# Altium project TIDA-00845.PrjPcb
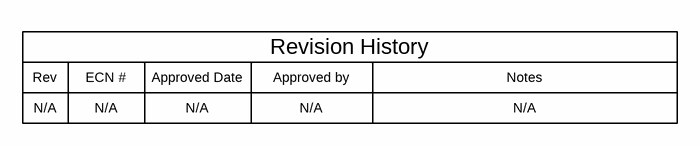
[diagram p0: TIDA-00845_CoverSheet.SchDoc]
TID: 00845; TechSupport: http://www.ti.com/support; SCH_Rev: A; PRJ_Title: USB2.0 Hub with STB Protection; PRJ_Number: TIDA-00845; PRJ_Engineer: Guy Yater; PRJ_Customer: Public Release; PCB_Rev: A; PCB_Layout: Guy Yater; EVM_Orderable: N/A; CopyrightYear: 2016
5 sheets, 144 parts. Net scope: flat (ports and power ports of the same name join across sheets).
Board file: TIDA-00845_TID.PcbDoc
Sheets:
  TIDA-00845_CoverSheet.SchDoc
  TIDA-00845_SCH.SchDoc
  TIDA-00845_TID_Hardware.SchDoc
  TIDA-00845_Enclosure_Machining.SchDoc
  TIDA-00845_Enclosure.SchDoc

## Sheet TIDA-00845_CoverSheet.SchDoc
size 431 x 279 mm; Date: Not shown in title block; ApprovedBy: Not shown in title block; CheckedBy: Not shown in title block; Author: Not shown in title block; CompanyName: Not shown in title block; Engineer: Not shown in title block; Organization: Not shown in title block; Address1: Not shown in title block; Address2: Not shown in title block; Address3: Not shown in title block; Address4: Not shown in title block; DocumentNumber: 1; Revision: Use project parameter SCH_Rev; SheetNumber: 1; SheetTotal: 3; PageSetup: Record=PageOptions¦CenterHorizontal=True¦CenterVertical=True¦PrintScale=1.00¦XCorrection=1.00¦YCorrection=1.00¦PrintKind=0¦BorderSize=5000000¦LeftOffset=0¦BottomOffset=0¦Orientation=2¦PaperLength=1000¦PaperWidth=1000¦Scale=100¦PaperSource=15¦PrintQuality=600¦MediaType=1¦DitherType=10¦PaperKind=Letter¦PrintScaleMode=1

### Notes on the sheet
- Rev
- N/A
- ECN #
- Approved Date
- Approved by
- Revision History
- Notes

## Sheet TIDA-00845_SCH.SchDoc
size 431 x 279 mm; Date: Not shown in title block; ApprovedBy: Not shown in title block; CheckedBy: Not shown in title block; Author: Not shown in title block; CompanyName: Not shown in title block; Engineer: Not shown in title block; Organization: Not shown in title block; Address1: Not shown in title block; Address2: Not shown in title block; Address3: Not shown in title block; Address4: Not shown in title block; DocumentNumber: 1; Revision: Use project parameter SCH_Rev; SheetNumber: 2; SheetTotal: 3; PageSetup: Record=PageOptions¦CenterHorizontal=True¦CenterVertical=True¦PrintScale=1.00¦XCorrection=1.00¦YCorrection=1.00¦PrintKind=0¦BorderSize=5000000¦LeftOffset=0¦BottomOffset=0¦Orientation=2¦PaperLength=1000¦PaperWidth=1000¦Scale=100¦PaperSource=15¦PrintQuality=600¦MediaType=1¦DitherType=10¦PaperKind=Letter¦PrintScaleMode=1
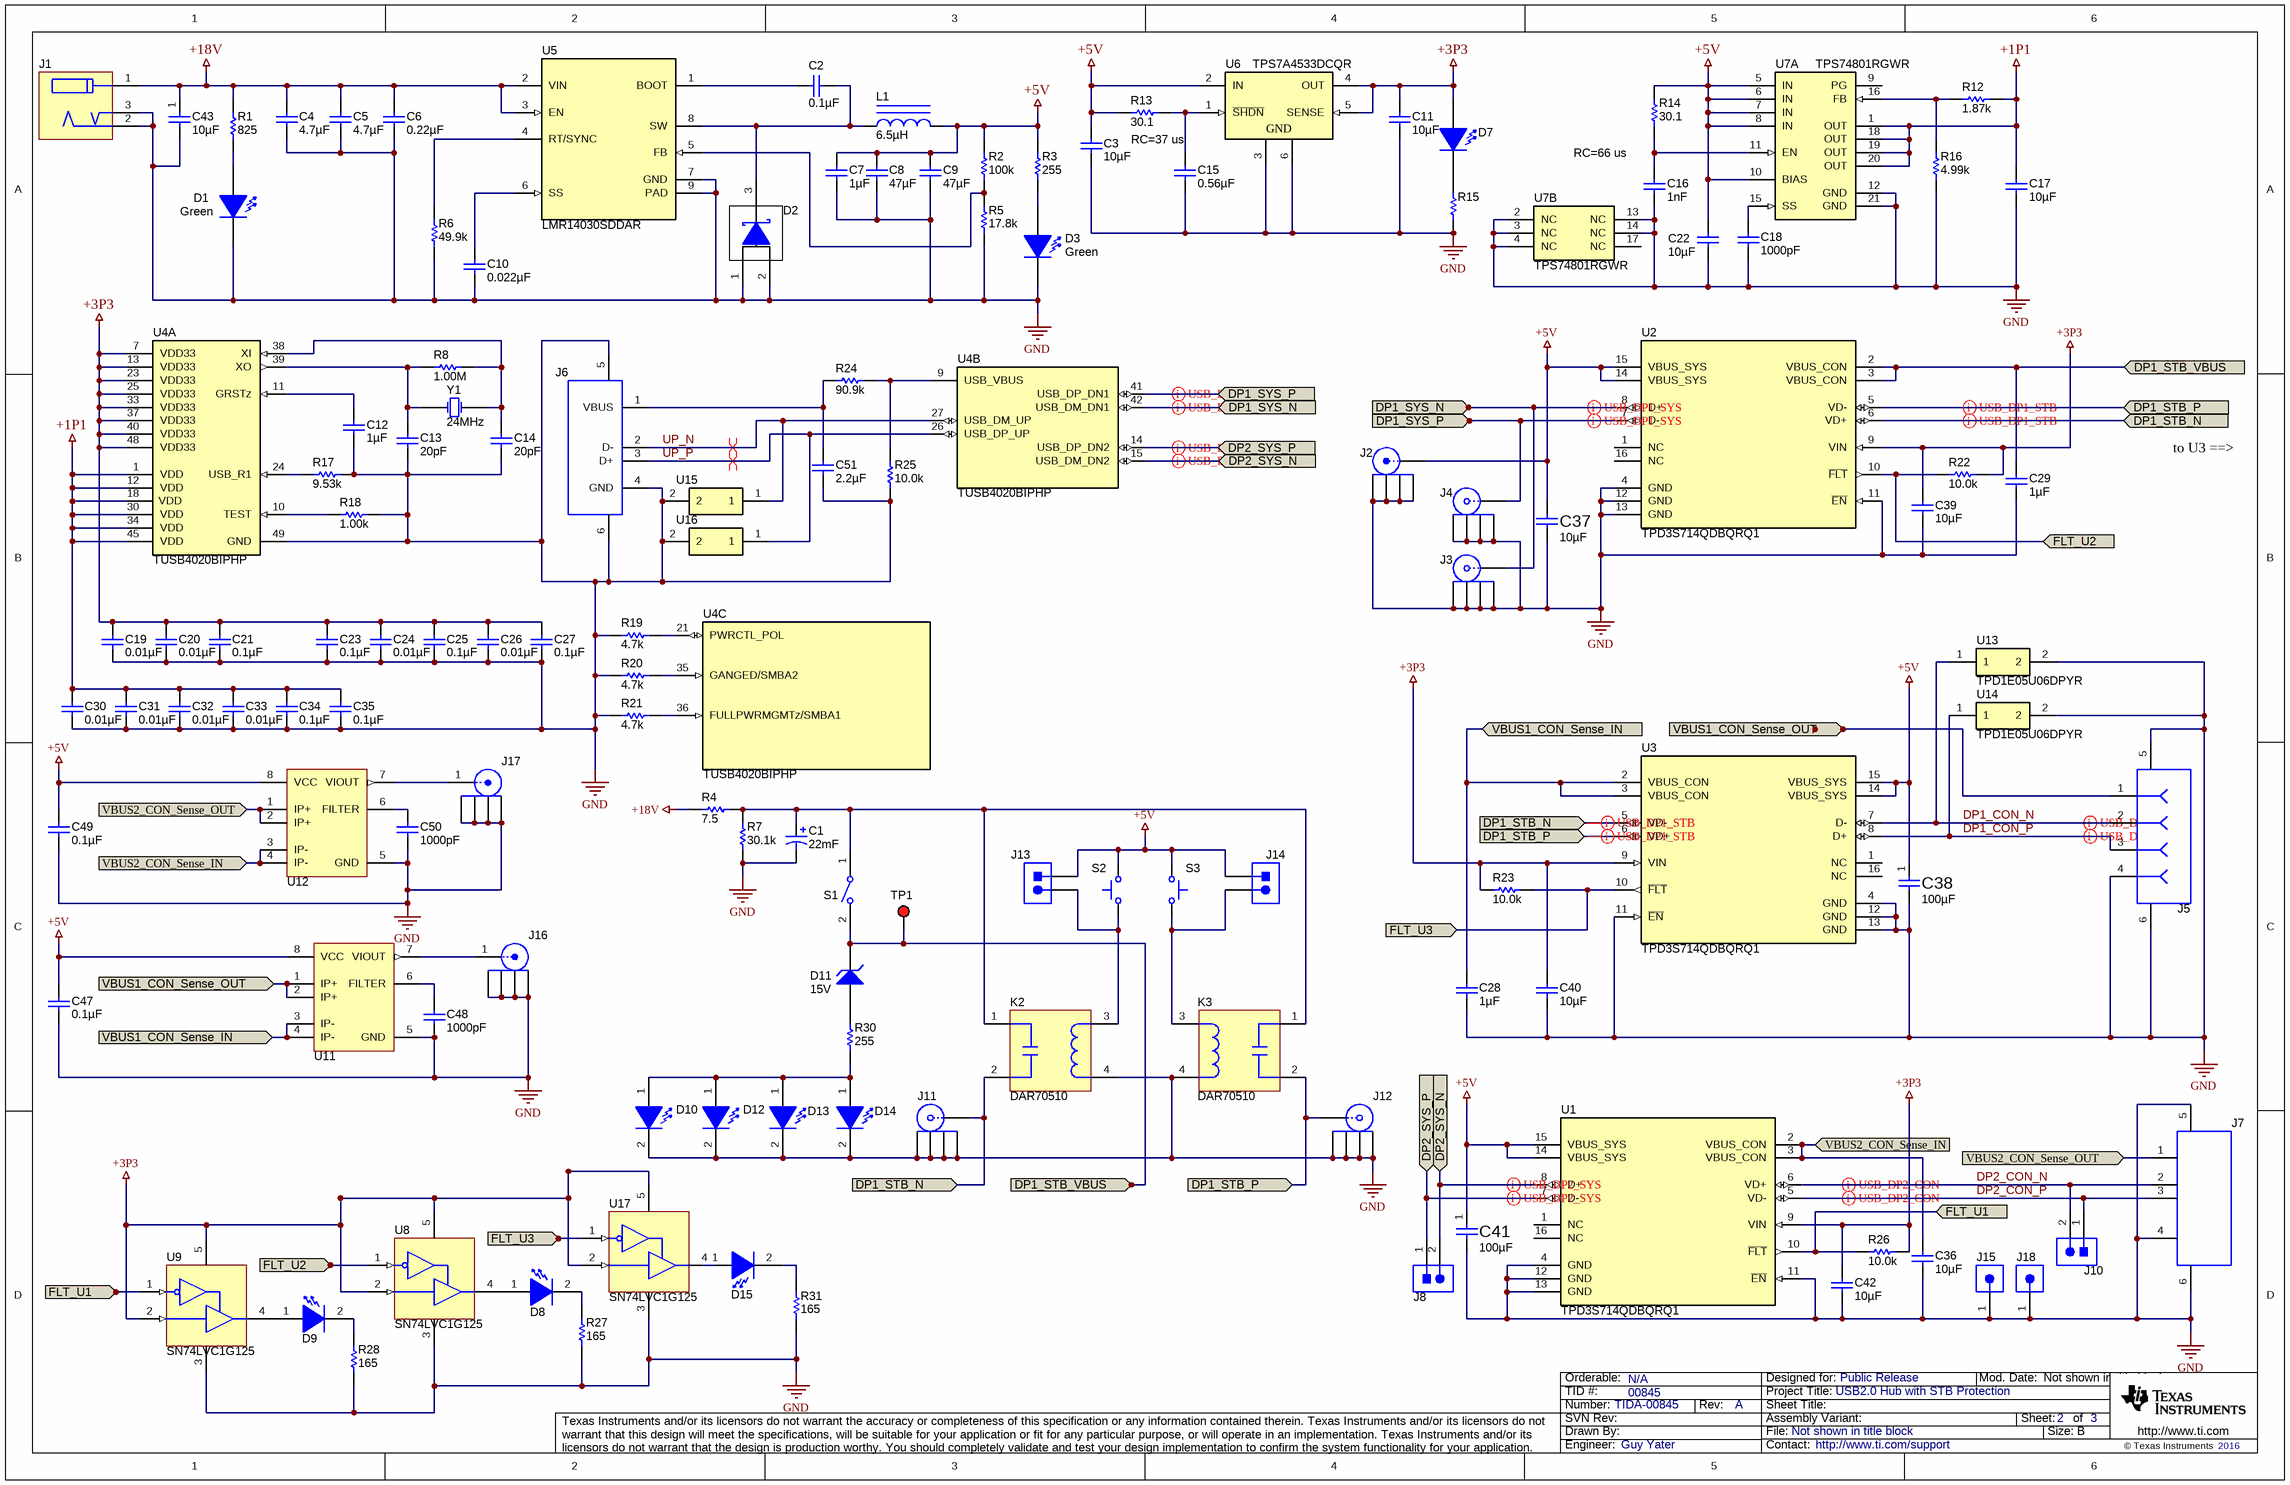
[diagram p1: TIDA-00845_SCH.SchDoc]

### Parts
C1  ValueDisplayed: 22mF  [EKMH350VSN223MA50T]  (hidden comment: B41231B5229M)
C2  ValueDisplayed: 0.1µF  [0603]  (hidden comment: GRM188R71C104KA01D)
C3  ValueDisplayed: 10µF  [0805_HV]  (hidden comment: 0805YD106MAT2A)
C4  ValueDisplayed: 4.7µF  [1210]  (hidden comment: GRM32ER71H475KA88L)
C5  ValueDisplayed: 4.7µF  [1210]  (hidden comment: GRM32ER71H475KA88L)
C6  ValueDisplayed: 0.22µF  [0805_HV]  (hidden comment: GRM21BR71H224KA01L)
C7  ValueDisplayed: 1µF  [0805_HV]  (hidden comment: GRM21BR71E105KA99L)
C8  ValueDisplayed: 47µF  [1210]  (hidden comment: GRM32ER61C476ME15L)
C9  ValueDisplayed: 47µF  [1210]  (hidden comment: GRM32ER61C476ME15L)
C10  ValueDisplayed: 0.022µF  [0402]  (hidden comment: GRM155R71C223KA01D)
C11  ValueDisplayed: 10µF  [0805_HV]  (hidden comment: 0805YD106MAT2A)
C12  ValueDisplayed: 1µF  [0402]  (hidden comment: GRM155R70J105MA12D)
C13  ValueDisplayed: 20pF  [0402]  (hidden comment: GRM1555C1H200JA01D)
C14  ValueDisplayed: 20pF  [0402]  (hidden comment: GRM1555C1H200JA01D)
C15  ValueDisplayed: 0.56µF  [1206]  (hidden comment: C1206C564K5RACTU)
C16  ValueDisplayed: 1nF  [1206_190]  (hidden comment: 202R18W102KV4E)
C17  ValueDisplayed: 10µF  [0805_HV]  (hidden comment: 0805YD106MAT2A)
C18  ValueDisplayed: 1000pF  [1206_190]  (hidden comment: 202R18W102KV4E)
C19  ValueDisplayed: 0.01µF  [0402]  (hidden comment: GRM155R71H103KA88D)
C20  ValueDisplayed: 0.01µF  [0402]  (hidden comment: GRM155R71H103KA88D)
C21  ValueDisplayed: 0.1µF  [0402]  (hidden comment: TMK105B7104MV-FR)
C22  ValueDisplayed: 10µF  [0805_HV]  (hidden comment: 0805YD106MAT2A)
C23  ValueDisplayed: 0.1µF  [0402]  (hidden comment: TMK105B7104MV-FR)
C24  ValueDisplayed: 0.01µF  [0402]  (hidden comment: GRM155R71H103KA88D)
C25  ValueDisplayed: 0.1µF  [0402]  (hidden comment: TMK105B7104MV-FR)
C26  ValueDisplayed: 0.01µF  [0402]  (hidden comment: GRM155R71H103KA88D)
C27  ValueDisplayed: 0.1µF  [0402]  (hidden comment: TMK105B7104MV-FR)
C28  ValueDisplayed: 1µF  [0603]  (hidden comment: UMK107AB7105KA-T)
C29  ValueDisplayed: 1µF  [0603]  (hidden comment: UMK107AB7105KA-T)
C30  ValueDisplayed: 0.01µF  [0402]  (hidden comment: GRM155R71H103KA88D)
C31  ValueDisplayed: 0.01µF  [0402]  (hidden comment: GRM155R71H103KA88D)
C32  ValueDisplayed: 0.01µF  [0402]  (hidden comment: GRM155R71H103KA88D)
C33  ValueDisplayed: 0.01µF  [0402]  (hidden comment: GRM155R71H103KA88D)
C34  ValueDisplayed: 0.1µF  [0402]  (hidden comment: TMK105B7104MV-FR)
C35  ValueDisplayed: 0.1µF  [0402]  (hidden comment: TMK105B7104MV-FR)
C36  ValueDisplayed: 10µF  [CKG57N]  (hidden comment: CKG57NX7R2A106M500JH)
C37  ValueDisplayed: 10µF  [1210_280]  (hidden comment: C1210C107M8PACTU)
C38  ValueDisplayed: 100µF  [1210_280]  (hidden comment: C1210C107M8PACTU)
C39  ValueDisplayed: 10µF  [0805L]  (hidden comment: C2012X7R0J106M125AB)
C40  ValueDisplayed: 10µF  [0805L]  (hidden comment: C2012X7R0J106M125AB)
C41  ValueDisplayed: 100µF  [1210_280]  (hidden comment: C1210C107M8PACTU)
C42  ValueDisplayed: 10µF  [0805L]  (hidden comment: C2012X7R0J106M125AB)
C43  ValueDisplayed: 10µF  [CKG57N]  (hidden comment: CKG57NX7R2A106M500JH)
C47  ValueDisplayed: 0.1µF  [0603]  (hidden comment: 06033C104JAT2A)
C48  ValueDisplayed: 1000pF  [0402]  (hidden comment: 885012205044)
C49  ValueDisplayed: 0.1µF  [0603]  (hidden comment: 06033C104JAT2A)
C50  ValueDisplayed: 1000pF  [0402]  (hidden comment: 885012205044)
C51  ValueDisplayed: 2.2µF  [0402]  (hidden comment: JMK105BJ225MV-F)
D1  value Green  [LED_LTST-C171]  (hidden comment: LTST-C171GKT)
D2  PDS560-13  [PowerDI5]  (value not drawn)
D3  value Green  [LED_LTST-C171]  (hidden comment: LTST-C171GKT)
D7  LTST-C171GKT  [LED_LTST-C171]  (value not drawn)
D8  VLMS1500-GS08  [VLMx1500_Red]  (value not drawn)
D9  VLMS1500-GS08  [VLMx1500_Red]  (value not drawn)
D10  VLMS1500-GS08  [VLMx1500_Red]  (value not drawn)
D11  value 15V  [SMA]  (hidden comment: 1SMA5929BT3G)
D12  VLMS1500-GS08  [VLMx1500_Red]  (value not drawn)
D13  VLMS1500-GS08  [VLMx1500_Red]  (value not drawn)
D14  VLMS1500-GS08  [VLMx1500_Red]  (value not drawn)
D15  VLMS1500-GS08  [VLMx1500_Red]  (value not drawn)
J1  PJ-202AH  [CONN_CUI-PJ-202AH]  (value not drawn)
J2  131-3701-261  [CONN_131-3701-261]  (value not drawn)
J3  131-5031-00  [Tek_131-5031-00]  (value not drawn)
J4  131-5031-00  [Tek_131-5031-00]  (value not drawn)
J5  292303-4  [CONN_TE_292303-4]  (value not drawn)
J6  67068-8000  [MOLEX_67068-8000]  (value not drawn)
J7  896-43-004-00-000000  [CONN_USB_896-43-004-00-000000]  (value not drawn)
J8  800-10-002-10-001000  [Mill-Max_800-10-002-10-001000]  (value not drawn)
J10  800-10-002-10-001000  [Mill-Max_800-10-002-10-001000]  (value not drawn)
J11  131-5031-00  [Tek_131-5031-00]  (value not drawn)
J12  131-5031-00  [Tek_131-5031-00]  (value not drawn)
J13  22-23-2021  [Molex_22-23-2021]  (value not drawn)
J14  22-23-2021  [Molex_22-23-2021]  (value not drawn)
J15  61300111121  [WURTH_61300111121]  (value not drawn)
J16  131-3701-261  [CONN_131-3701-261]  (value not drawn)
J17  131-3701-261  [CONN_131-3701-261]  (value not drawn)
J18  61300111121  [WURTH_61300111121]  (value not drawn)
K2  DAR70510  [DAR70510]
K3  DAR70510  [DAR70510]
L1  ValueDisplayed: 6.5µH  [WE-HCI_7050]  (hidden comment: 744314650)
R1  ValueDisplayed: 825  [0402]  (hidden comment: CRCW0402825RFKED)
R2  ValueDisplayed: 100k  [0402]  (hidden comment: CRCW0402100KDHEDP)
R3  ValueDisplayed: 255  [0402]  (hidden comment: CRCW0402255RFKED)
R4  ValueDisplayed: 7.5  [TEH100M7R50FE]  (hidden comment: TEH100M7R50FE)
R5  ValueDisplayed: 17.8k  [0402]  (hidden comment: CRCW040217K8FKED)
R6  ValueDisplayed: 49.9k  [0402]  (hidden comment: CRCW040249K9FKED)
R7  ValueDisplayed: 30.1k  [0402]  (hidden comment: CRCW040230K1FKED)
R8  ValueDisplayed: 1.00M  [0402]  (hidden comment: CRCW04021M00FKED)
R12  ValueDisplayed: 1.87k  [0402]  (hidden comment: CRCW04021K87FKED)
R13  ValueDisplayed: 30.1  [0402]  (hidden comment: CRCW040230R1FKED)
R14  ValueDisplayed: 30.1  [0402]  (hidden comment: CRCW040230R1FKED)
R15  CRCW0402330RJNED  [0402]  (value not drawn)
R16  ValueDisplayed: 4.99k  [0402]  (hidden comment: CRCW04024K99FKED)
R17  ValueDisplayed: 9.53k  [0402]  (hidden comment: CRCW04029K53FKED)
R18  ValueDisplayed: 1.00k  [0402]  (hidden comment: CRCW04021K00FKED)
R19  ValueDisplayed: 4.7k  [0402]  (hidden comment: CRCW04024K70JNED)
R20  ValueDisplayed: 4.7k  [0402]  (hidden comment: CRCW04024K70JNED)
R21  ValueDisplayed: 4.7k  [0402]  (hidden comment: CRCW04024K70JNED)
R22  value 10.0k  [0603]  (hidden comment: CRCW060310K0FKEA)
R23  value 10.0k  [0603]  (hidden comment: CRCW060310K0FKEA)
R24  ValueDisplayed: 90.9k  [0402]  (hidden comment: CRCW040290K9FKED)
R25  ValueDisplayed: 10.0k  [0402]  (hidden comment: CRCW040210K0DHEDP)
R26  value 10.0k  [0603]  (hidden comment: CRCW060310K0FKEA)
R27  ValueDisplayed: 165  [0402]  (hidden comment: CRCW0402165RFKED)
R28  ValueDisplayed: 165  [0402]  (hidden comment: CRCW0402165RFKED)
R30  ValueDisplayed: 255  [0402]  (hidden comment: CRCW0402255RFKED)
R31  ValueDisplayed: 165  [0402]  (hidden comment: CRCW0402165RFKED)
S1  GPB527C202BR  [GPB527C202BR]  (value not drawn)
S2  KSR221GLFS  [KSR]  (value not drawn)
S3  KSR221GLFS  [KSR]  (value not drawn)
TP1  5000  [Keystone5000]  (value not drawn)
U1  TPD3S714QDBQRQ1  [DBQ0016A_N]
U2  TPD3S714QDBQRQ1  [DBQ0016A_N]
U3  TPD3S714QDBQRQ1  [DBQ0016A_N]
U4  TUSB4020BIPHP  [PHP0048C_N]  (parts A,B,C of 4)
U5  LMR14030SDDAR  [DDA0008E_N]
U6  TPS7A4533DCQR  [DCQ0006A_N]
U7  TPS74801RGWR  [RGW0020A]  (parts A,B of 2)
U8  SN74LVC1G125  [DCK0005A_N]
U9  SN74LVC1G125  [DCK0005A_N]
U11  ACS712ELCTR-05B-T  [SOIC-8]  (value not drawn)
U12  ACS712ELCTR-05B-T  [SOIC-8]  (value not drawn)
U13  TPD1E05U06DPYR  [DPY0002A]
U14  TPD1E05U06DPYR  [DPY0002A]
U15  TPD1E05U06DPYR  [DPY0002A]  (value not drawn)
U16  TPD1E05U06DPYR  [DPY0002A]  (value not drawn)
U17  SN74LVC1G125  [DCK0005A_N]
Y1  Frequency: 24MHz  [445C25D24M00000]  (hidden comment: 445C25D24M00000)

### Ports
DP1_STB_N, DP1_STB_P, DP1_STB_VBUS, DP1_SYS_N, DP1_SYS_P, DP2_SYS_N, DP2_SYS_P, FLT_U1, FLT_U2, FLT_U3, VBUS1_CON_Sense_IN, VBUS1_CON_Sense_OUT, VBUS2_CON_Sense_IN, VBUS2_CON_Sense_OUT

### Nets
+1P1: C17.1 C30.2 C31.2 C32.2 C33.2 C34.2 C35.2 R12.2 U4.1(VDD) U4.12(VDD) U4.18(VDD) U4.30(VDD) U4.34(VDD) U4.45(VDD) U7.1(OUT) U7.18(OUT) U7.19(OUT) U7.20(OUT)
+3P3: C11.1 C19.2 C20.2 C21.2 C23.2 C24.2 C25.2 C26.2 C27.2 C39.1 C40.1 C42.1 D7.1(A) R22.2 R23.1 R26.2 U1.9(VIN) U2.9(VIN) U3.9(VIN) U4.7(VDD33) U4.13(VDD33) U4.23(VDD33) U4.25(VDD33) U4.33(VDD33) U4.37(VDD33) U4.40(VDD33) U4.48(VDD33) U6.4(OUT) U6.5(SENSE) U8.2(A) U8.5(VCC) U9.2(A) U9.5(VCC) U17.2(A) U17.5(VCC)
+5V: C3.1 C7.1 C8.1 C9.1 C22.1 C37.1 C38.1 C41.1 C47.1 C49.1 J2.1 J13.1 J14.1 L1.2 R2.1 R3.1 R13.2 R14.2 S2.2 S3.2 U1.14(VBUS_SYS) U1.15(VBUS_SYS) U2.14(VBUS_SYS) U2.15(VBUS_SYS) U3.14(VBUS_SYS) U3.15(VBUS_SYS) U6.2(IN) U7.5(IN) U7.6(IN) U7.7(IN) U7.8(IN) U7.10(BIAS) U11.8(VCC) U12.8(VCC)
+18V: C4.2 C5.2 C6.2 C43.1 J1.1 R1.2 R4.1 U5.2(VIN) U5.3(EN)
GND: C1.2(-) C3.2 C4.1 C5.1 C6.1 C7.2 C8.2 C9.2 C10.1 C11.2 C12.1 C13.2 C14.2 C15.1 C16.1 C17.2 C18.1 C19.1 C20.1 C21.1 C22.2 C23.1 C24.1 C25.1 C26.1 C27.1 C28.2 C29.2 C30.1 C31.1 C32.1 C33.1 C34.1 C35.1 C36.2 C37.2 C38.2 C39.2 C40.2 C41.2 C42.2 C43.2 C47.2 C48.2 C49.2 C50.2 C51.2 D1.2(K) D2.1(A) D2.2(A) D3.2(K) D10.2(K) D12.2(K) D13.2(K) D14.2(K) J1.2 J1.3 J2.2 J2.3 J2.4 J2.5 J3.2 J3.3 J3.4 J3.5 J4.2 J4.3 J4.4 J4.5 J5.4 J5.5 J5.6 J6.4(GND) J6.5(Shield) J6.6(Shield) J7.4(ID) J7.5(Shield) J7.6(Shield) J11.2 J11.3 J11.4 J11.5 J12.2 J12.3 J12.4 J12.5 J15.1 J16.2 J16.3 J16.4 J16.5 J17.2 J17.3 J17.4 J17.5 J18.1 K2.4 K3.4 R5.2 R6.2 R7.1 R15.1 R16.1 R17.2 R18.2 R19.1 R20.1 R21.1 R25.1 R27.2 R28.2 R31.2 U1.4(GND) U1.11(~{EN}) U1.12(GND) U1.13(GND) U2.4(GND) U2.11(~{EN}) U2.12(GND) U2.13(GND) U3.4(GND) U3.11(~{EN}) U3.12(GND) U3.13(GND) U4.49(GND) U5.7(GND) U5.9(PAD) U6.3(GND) U6.6(GND) U7.2(NC) U7.3(NC) U7.4(NC) U7.12(GND) U7.13(NC) U7.14(NC) U7.21(GND) U8.3(GND) U9.3(GND) U11.5(GND) U12.5(GND) U13.2 U14.2 U15.2 U16.2 U17.3(GND)
DP1_CON_N: J5.2 U3.7(D-) U13.1
DP1_CON_P: J5.3 U3.8(D+) U14.1
DP1_STB_N: J11.1 K2.2 U2.6(VD+) U3.5(VD-) ; port DP1_STB_N
DP1_STB_P: J12.1 K3.2 U2.5(VD-) U3.6(VD+) ; port DP1_STB_P
DP1_STB_VBUS: C29.1 D11.1(K) S1.2 TP1.1 U2.2(VBUS_CON) U2.3(VBUS_CON) ; port DP1_STB_VBUS
DP1_SYS_N: J3.1 U2.8(D+) U4.42(USB_DM_DN1) ; port DP1_SYS_N
DP1_SYS_P: J4.1 U2.7(D-) U4.41(USB_DP_DN1) ; port DP1_SYS_P
DP2_CON_N: J7.2(D-) J10.2 U1.6(VD+)
DP2_CON_P: J7.3(D+) J10.1 U1.5(VD-)
DP2_SYS_N: J8.2 U1.8(D+) U4.15(USB_DM_DN2) ; port DP2_SYS_N
DP2_SYS_P: J8.1 U1.7(D-) U4.14(USB_DP_DN2) ; port DP2_SYS_P
FLT_U1: R26.1 U1.10(~{FLT}) U9.1(~{OE}) ; port FLT_U1
FLT_U2: R22.1 U2.10(~{FLT}) U8.1(~{OE}) ; port FLT_U2
FLT_U3: R23.2 U3.10(~{FLT}) U17.1(~{OE}) ; port FLT_U3
UP_N: J6.2(D-) U4.27(USB_DM_UP) U15.1
UP_P: J6.3(D+) U4.26(USB_DP_UP) U16.1
VBUS1_CON_Sense_IN: C28.1 U3.2(VBUS_CON) U3.3(VBUS_CON) U11.3(IP-) U11.4(IP-) ; port VBUS1_CON_Sense_IN
VBUS1_CON_Sense_OUT: J5.1 U11.1(IP+) U11.2(IP+) ; port VBUS1_CON_Sense_OUT
VBUS2_CON_Sense_IN: C36.1 U1.2(VBUS_CON) U1.3(VBUS_CON) U12.3(IP-) U12.4(IP-) ; port VBUS2_CON_Sense_IN
VBUS2_CON_Sense_OUT: J7.1(VBUS) U12.1(IP+) U12.2(IP+) ; port VBUS2_CON_Sense_OUT
NetC1_1: C1.1(+) K2.1 K3.1 R4.2 R7.2 S1.1
NetC2_1: C2.1 D2.3(K) L1.1 U5.8(SW)
NetC2_2: C2.2 U5.1(BOOT)
NetC10_2: C10.2 U5.6(SS)
NetC12_2: C12.2 U4.11(GRSTz)
NetC13_1: C13.1 R8.1 U4.39(XO) Y1.1(OSC1)
NetC14_1: C14.1 R8.2 U4.38(XI) Y1.2(OSC2)
NetC15_2: C15.2 R13.1 U6.1(~{SHDN})
NetC16_2: C16.2 R14.1 U7.11(EN)
NetC18_2: C18.2 U7.15(SS)
NetC48_1: C48.1 U11.6(FILTER)
NetC50_1: C50.1 U12.6(FILTER)
NetC51_1: C51.1 J6.1(VBUS) R24.1
NetD1_1: D1.1(A) R1.1
NetD3_1: D3.1(A) R3.2
NetD7_2: D7.2(K) R15.2
NetD8_1: D8.1(A) U8.4(Y)
NetD8_2: D8.2(K) R27.1
NetD9_1: D9.1(A) U9.4(Y)
NetD9_2: D9.2(K) R28.1
NetD10_1: D10.1(A) D12.1(A) D13.1(A) D14.1(A) R30.2
NetD11_2: D11.2(A) R30.1
NetD15_1: D15.1(A) U17.4(Y)
NetD15_2: D15.2(K) R31.1
NetJ13_2: J13.2 K2.3 S2.1
NetJ14_2: J14.2 K3.3 S3.1
NetJ16_1: J16.1 U11.7(VIOUT)
NetJ17_1: J17.1 U12.7(VIOUT)
NetR2_2: R2.2 R5.1 U5.5(FB)
NetR6_1: R6.1 U5.4(RT/SYNC)
NetR12_1: R12.1 R16.2 U7.16(FB)
NetR17_1: R17.1 U4.24(USB_R1)
NetR18_1: R18.1 U4.10(TEST)
NetR19_2: R19.2 U4.21(PWRCTL_POL)
NetR20_2: R20.2 U4.35(GANGED/SMBA2)
NetR21_2: R21.2 U4.36(FULLPWRMGMTz/SMBA1)
NetR24_2: R24.2 R25.2 U4.9(USB_VBUS)

Not connected (* = marked no-connect by the designer): U1 1(NC) 16(NC); U2 1(NC) 16(NC); U3 1(NC) 16(NC); U7 9(PG) 17(NC)

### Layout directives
differential pair: DP1_CON_N, DP1_CON_P, DP1_STB_N, DP1_STB_P, DP1_SYS_N, DP1_SYS_P, DP2_CON_N, DP2_CON_P, DP2_SYS_N, DP2_SYS_P, UP_N, UP_P

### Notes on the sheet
- RC=37 us
- RC=66 us
- to U3 ==>

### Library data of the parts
C1 = EMVA6R3GTR103MMN0S: CAP, AL, 10000 µF, 6.3 V, +/- 20%, SMD; Manufacturer: EPCOS (TDK); Polarized: Y; CompType: Capacitor; Value: 22000uF; U/M: EA; Cap_F: .022; Tolerance_%: 20; Value1: Unknown; VDC_V: 25V; IRMS_A: 2; TaMin_C: -40; TaMax_C: 85; Cap_Case: MN0; AEC Category: Q200
C2 = GRM188R71C104KA01D: CAP, CERM, 0.1 µF, 16 V, +/- 10%, X7R, 0603; Manufacturer: MuRata; Polarized: N; CompType: Capacitor; Value: 0.1uF; U/M: EA; Cap_F: 0.0000001; Tolerance_%: 10; Value1: Unknown; VDC_V: 16; Value2: 16V; TaMin_C: -55; TaMax_C: 125; AEC Category: Q200
C3 C11 C17 C22 = 0805YD106MAT2A: CAP, CERM, 10 µF, 16 V, +/- 20%, X5R, 0805; Manufacturer: AVX; Polarized: N; CompType: Capacitor; Value: 10uF; U/M: EA; Cap_F: 0.00001; Tolerance_%: 20; Value1: Unknown; VDC_V: 16; Value2: 16V; TaMin_C: -55; TaMax_C: 85; Cap_Case: 0805; AEC Category: Q200
C4 C5 = GRM32ER71H475KA88L: CAP, CERM, 4.7 µF, 50 V, +/- 10%, X7R, 1210; Manufacturer: MuRata; Polarized: N; CompType: Capacitor; Value: 4.7uF; U/M: EA; Cap_F: 0.0000047; Tolerance_%: 10; ESR_ohm: 0.002; Value1: 0.002 ohm; VDC_V: 50; Value2: 50V; TaMin_C: -55; TaMax_C: 125; AEC Category: Q200
C6 = GRM21BR71H224KA01L: CAP, CERM, 0.22 µF, 50 V, +/- 10%, X7R, 0805; Manufacturer: MuRata; Polarized: N; CompType: Capacitor; Value: 0.22uF; U/M: EA; Cap_F: 0.00000022; Tolerance_%: 10; Value1: Unknown; VDC_V: 50; Value2: 50V; TaMin_C: -55; TaMax_C: 125; Cap_Case: 0805; AEC Category: Q200
C7 = GRM21BR71E105KA99L: CAP, CERM, 1 µF, 25 V, +/- 10%, X7R, 0805; Manufacturer: MuRata; Polarized: N; CompType: Capacitor; Value: 1uF; U/M: EA; Cap_F: 0.000001; Tolerance_%: 10; Value1: Unknown; VDC_V: 25; Value2: 25V; TaMin_C: -55; TaMax_C: 125; Cap_Case: 0805; AEC Category: Q200
C8 C9 = GRM32ER61C476ME15L: CAP, CERM, 47 µF, 16 V, +/- 20%, X5R, 1210; Manufacturer: MuRata; Polarized: N; CompType: Capacitor; Value: 47uF; U/M: EA; Cap_F: 0.000047; Tolerance_%: 20; ESR_ohm: 0.002; Value1: 0.002 ohm; VDC_V: 16; Value2: 16V; TaMin_C: -55; TaMax_C: 85; AEC Category: Q200
C10 = GRM155R71C223KA01D: CAP, CERM, 0.022 µF, 16 V, +/- 10%, X7R, 0402; Manufacturer: MuRata; Polarized: N; CompType: Capacitor; Value: 0.022uF; U/M: EA; Cap_F: 0.000000022; Tolerance_%: 10; Value1: Unknown; VDC_V: 16; Value2: 16V; TaMin_C: -55; TaMax_C: 125; AEC Category: Q200
C12 = GRM155R70J105MA12D: CAP, CERM, 1 µF, 6.3 V, +/- 20%, X7R, 0402; Manufacturer: MuRata; Polarized: N; CompType: Capacitor; Value: 1uF; U/M: EA; Cap_F: 0.000001; Tolerance_%: 20; Value1: Unknown; VDC_V: 6.3; Value2: 6.3V; TaMin_C: -55; TaMax_C: 125; AEC Category: Q200
C13 C14 = GRM1555C1H200JA01D: CAP, CERM, 20 pF, 50 V, +/- 5%, C0G/NP0, 0402; Manufacturer: MuRata; Polarized: N; CompType: Capacitor; Value: 20pF; U/M: EA; Cap_F: 0.00000000002; Tolerance_%: 5; Value1: Unknown; VDC_V: 50; Value2: 50V; TaMin_C: -55; TaMax_C: 125; AEC Category: Q200
C15 = 12063C564KAT2A: CAP, CERM, 0.56 µF, 25 V, +/- 10%, X7R, 1206; Manufacturer: AVX; Polarized: N; CompType: Capacitor; Value: 0.56uF; U/M: EA; Cap_F: 0.00000056; Tolerance_%: 10; ESR_ohm: 0.017; Value1: 0.017 ohm; VDC_V: 25; Value2: 25V; TaMin_C: -55; TaMax_C: 125; AEC Category: Q200
C16 C18 = 202R18W102KV4E: CAP, CERM, 1000 pF, 2000 V, +/- 10%, X7R, 1206_190; Manufacturer: Johanson Technology; Polarized: N; CompType: Capacitor; Value: 1000pF; U/M: EA; Cap_F: 0.000000001; Tolerance_%: 10; Value1: Unknown; VDC_V: 2000; Value2: 2000V; TaMin_C: -55; TaMax_C: 125; Cap_Case: 1206; AEC Category: Q200
C19 C20 C24 C26 C30-C33 = GRM155R71H103KA88D: CAP, CERM, 0.01 µF, 50 V, +/- 10%, X7R, 0402; Manufacturer: MuRata; Polarized: N; CompType: Capacitor; Value: 0.01uF; U/M: EA; Cap_F: 0.00000001; Tolerance_%: 10; Value1: Unknown; VDC_V: 50; Value2: 50V; TaMin_C: -55; TaMax_C: 125; AEC Category: Q200
C21 C23 C25 C27 C34 C35 = TMK105B7104MV-FR: CAP, CERM, 0.1 µF, 25 V, +/- 20%, X7R, 0402; Manufacturer: Taiyo Yuden; Polarized: N; CompType: Capacitor; Value: 0.1uF; U/M: EA; Cap_F: 0.0000001; Tolerance_%: 20; Value1: Unknown; VDC_V: 25; Value2: 25V; TaMin_C: -55; TaMax_C: 125; AEC Category: Q200
C28 C29 = UMK107AB7105KA-T: CAP, CERM, 1 µF, 50 V, +/- 10%, X7R, 0603; Manufacturer: Taiyo Yuden; Polarized: N; CompType: Capacitor; Value: 1uF; U/M: EA; Cap_F: 0.000001; Tolerance_%: 10; Value1: Unknown; VDC_V: 50; Value2: 50V; TaMin_C: -55; TaMax_C: 125; AEC Category: Q200
C36 C43 = CKG57NX7R2A106M500JH: CAP, CERM, 10 µF, 100 V, +/- 20%, X7R, 6x5x5mm; Manufacturer: TDK; Polarized: N; CompType: Capacitor; Value: 10uF; U/M: EA; Cap_F: 0.00001; Tolerance_%: 20; Value1: Unknown; VDC_V: 100; Value2: 100V; TaMin_C: -55; TaMax_C: 125; Cap_Case: 2220; AEC Category: Q200
C37 C38 C41 = C1210C107M8PACTU: CAP, CERM, 100 µF, 10 V, +/- 20%, X5R, 1210; Manufacturer: Wurth Elektronik; Polarized: N; CompType: Capacitor; Value: 100uF; U/M: EA; Cap_F: 0.0001; Tolerance_%: 20; Value1: Unknown; VDC_V: 10; Value2: 10V; TaMin_C: -55; TaMax_C: 85; Cap_Case: 1210
C39 C40 C42 = C2012X7R0J106M125AB: CAP, CERM, 10 µF, 6.3 V, +/- 20%, X7R, 0805; Manufacturer: TDK; Polarized: N; CompType: Capacitor; Value: 10uF; U/M: EA; Cap_F: 0.00001; Tolerance_%: 20; Value1: Unknown; VDC_V: 6.3; Value2: 6.3V; TaMin_C: -55; TaMax_C: 125; Cap_Case: 0805
C47 C49 = 06033C104JAT2A: CAP, CERM, 0.1 µF, 25 V, +/- 5%, X7R, 0603; Manufacturer: AVX; Polarized: N; CompType: Capacitor; Value: 0.1uF; U/M: EA; Cap_F: 0.0000001; Tolerance_%: 5; ESR_ohm: 0.05; Value1: 0.05 ohm; VDC_V: 25; Value2: 25V; TaMin_C: -55; TaMax_C: 125; AEC Category: Q200
C48 C50 = 885012205044: CAP, CERM, 1000 pF, 25 V, +/- 10%, X7R, 0402; Manufacturer: Wurth Elektronik; Polarized: N; CompType: Capacitor; Value: 1000pF; U/M: EA; Cap_F: 0.000000001; Tolerance_%: 10; Value1: Unknown; VDC_V: 25; Value2: 25V; TaMin_C: -55; TaMax_C: 125; AEC Category: Q200
C51 = JMK105BJ225MV-F: CAP, CERM, 2.2 µF, 6.3 V, +/- 20%, X5R, 0402; Manufacturer: Taiyo Yuden; Polarized: N; CompType: Capacitor; Value: 2.2uF; U/M: EA; Cap_F: 0.0000022; Tolerance_%: 20; ESR_ohm: 0.00152; Value1: 0.00152 ohm; VDC_V: 6.3; Value2: 6.3V; TaMin_C: -55; TaMax_C: 125; AEC Category: Q200
D1 D3 D7 = LTST-C171GKT: LED, Green, SMD; Manufacturer: Lite-On; Type: AlInGaP; Vf_V: 2.1; Value2: 2.1V; Io_A: 20; Value1: W; U/M: EA
D2 = PDS560-13: Diode, Schottky, 60 V, 5 A, PowerDI5; Manufacturer: Diodes Inc.; U/M: EA; Vf_V: 0.67; Value: 60V; Value1: 5A; Value2: 0.67V; Io_A: 5; Vr_V: 60; TJmax_C: 150; AEC Category: Q101
D8-D10 D12-D15 = VLMS1500-GS08: LED, Super Red, SMD; Manufacturer: Vishay-Semiconductor; Type: AlInGaP; Vf_V: 2; Value2: 2V; Io_A: 0.02; Value1: W; U/M: EA
D11 = 1SMA5929BT3G: Diode, Zener, 15 V, 500 mW, SMA; Manufacturer: ON Semiconductor; SymbolCreator: a0412235; U/M: EA; Power_W: 0.5; Vz_V: 15; Value1: 0.5W; AEC Category: Q101
J1 = PJ-202AH: Connector, DC Jack 2.1X5.5 mm, TH; Manufacturer: CUI Inc.; SymbolCreator: a0799628; CompType: Power Jack; U/M: EA
J2 J16 J17 = 131-3701-261: Connector, SMB,Vertical RCP 0-4GHz, 50 ohm, TH; Manufacturer: Emerson Network Power; U/M: EA
J3 J4 J11 J12 = 131-5031-00: Compact Probe Tip Circuit Board Test Points, TH, 25 per; Manufacturer: Tektronix; U/M: EA
J5 = 292303-4: Connector, Receptacle, USB Type A, R/A, Top Mount TH; Manufacturer: TE Connectivity; SymbolCreator: a0412235; U/M: EA
J6 = 67068-8000: Connector, Receptacle, USB TYPE B, R/A, Top Mount TH; Manufacturer: Molex; SymbolCreator: a0412235; U/M: EA
J7 = 896-43-004-00-000000: Connector, Receptacle, USB TYPE A, 4POS SMD; Manufacturer: Mill-Max; SymbolCreator: a0412235; U/M: EA
J8 J10 = 800-10-002-10-001000: Header, 100mil, 2x1, TH; Manufacturer: Mill-Max; SymbolCreator: a0412235; U/M: EA
J13 J14 = 22-23-2021: Header, 2.54mm, 2x1, Vertical, TH; Manufacturer: Molex; SymbolCreator: a0412235; U/M: EA
J15 J18 = 61300111121: Header, 2.54 mm, 1x1, Gold, TH; Manufacturer: Wurth Elektronik; SymbolCreator: a0412235; U/M: EA
K2 K3 = DAR70510: Manufacturer: Cynergy 3; SymbolCreator: a0273549; CompType: Used in some BOM reports.  Useful for finding later.; U/M: EA, IN, or GM
L1 = 744314650: Inductor, Shielded Drum Core, Superflux, 6.5 µH, 6 A, 0.0225 ohm, SMD; Manufacturer: Wurth Elektronik; Value: 6.5uH; Ind_H: 6.5E-6; Imax_A: 6; Irms: 6A @ 50C rise; Isat: 6A @ 30% inductance drop; DCR_ohm: 0.0225; Value2: 6A; AEC Category: Q200
R1 = CRCW0402825RFKED: RES, 825, 1%, 0.063 W, 0402; Manufacturer: Vishay-Dale; CompType: Resistor; Value: 825; Value_Code: 825R; Tolerance_%: 1; Power_W: 0.063; Value2: 0.063W; VDC_V: 50; TempCo: 100 ppm/C; EIA_Code: E96; U/M: EA; AEC Category: Q200
R2 = CRCW0402100KDHEDP: RES, 100 k, 0.5%, 0.063 W, 0402; Manufacturer: Vishay-Dale; CompType: Resistor; Value: 100k; Res_ohm: 100000; Tolerance_%: 0.5; Power_W: 0.063; Value2: 0.063W; VDC_V: 50; TempCo: 50 ppm/C; EIA_Code: E192; U/M: EA; AEC Category: Q200
R3 R30 = CRCW0402255RFKED: RES, 255, 1%, 0.063 W, 0402; Manufacturer: Vishay-Dale; CompType: Resistor; Value: 255; Value_Code: 255R; Tolerance_%: 1; Power_W: 0.063; Value2: 0.063W; VDC_V: 50; TempCo: 100 ppm/C; EIA_Code: E96; U/M: EA; AEC Category: Q200
R4 = SQP10AJB-7R5: RES, 7.5, 5%, 10 W, RES 48x9.5x9mm; Manufacturer: Ohmite; CompType: Resistor; Value: 7.5; Value_Code: 7R50; Tolerance_%: 5; Power_W: 100; Value2: 10W; VDC_V: 500; TempCo: 300 ppm/C; EIA_Code: E24; U/M: EA; AEC Category: Q200
R5 = CRCW040217K8FKED: RES, 17.8 k, 1%, 0.063 W, 0402; Manufacturer: Vishay-Dale; CompType: Resistor; Value: 17.8k; Res_ohm: 17800; Value_Code: 17k8; Tolerance_%: 1; Power_W: 0.063; Value2: 0.063W; VDC_V: 50; TempCo: 100 ppm/C; EIA_Code: E96; U/M: EA; AEC Category: Q200
R6 = CRCW040249K9FKED: RES, 49.9 k, 1%, 0.063 W, 0402; Manufacturer: Vishay-Dale; CompType: Resistor; Value: 49.9k; Res_ohm: 49900; Value_Code: 49k9; Tolerance_%: 1; Power_W: 0.063; Value2: 0.063W; VDC_V: 50; TempCo: 100 ppm/C; EIA_Code: E96; U/M: EA; AEC Category: Q200
R7 = CRCW040230K1FKED: RES, 30.1 k, 1%, 0.063 W, 0402; Manufacturer: Vishay-Dale; CompType: Resistor; Value: 30.1k; Res_ohm: 30100; Value_Code: 30k1; Tolerance_%: 1; Power_W: 0.063; Value2: 0.063W; VDC_V: 50; TempCo: 100 ppm/C; EIA_Code: E96; U/M: EA; AEC Category: Q200
R8 = CRCW04021M00FKED: RES, 1.00 M, 1%, 0.063 W, 0402; Manufacturer: Vishay-Dale; CompType: Resistor; Value: 1.00Meg; Res_ohm: 1000000; Value_Code: 1M00; Tolerance_%: 1; Power_W: 0.063; Value2: 0.063W; VDC_V: 50; TempCo: 100 ppm/C; EIA_Code: E96; U/M: EA; AEC Category: Q200
R12 = CRCW04021K87FKED: RES, 1.87 k, 1%, 0.063 W, 0402; Manufacturer: Vishay-Dale; CompType: Resistor; Value: 1.87k; Res_ohm: 1870; Value_Code: 1k87; Tolerance_%: 1; Power_W: 0.063; Value2: 0.063W; VDC_V: 50; TempCo: 100 ppm/C; EIA_Code: E96; U/M: EA; AEC Category: Q200
R13 R14 = CRCW040230R1FKED: RES, 30.1, 1%, 0.063 W, 0402; Manufacturer: Vishay-Dale; CompType: Resistor; Value: 30.1; Value_Code: 30R1; Tolerance_%: 1; Power_W: 0.063; Value2: 0.063W; VDC_V: 50; TempCo: 100 ppm/C; EIA_Code: E96; U/M: EA; AEC Category: Q200
R15 = CRCW0402330RJNED: RES, 330, 5%, 0.063 W, 0402; Manufacturer: Vishay-Dale; CompType: Resistor; Value: 330; Value_Code: 330R; Tolerance_%: 5; Power_W: 0.063; Value2: 0.063W; VDC_V: 50; TempCo: 200 ppm/C; EIA_Code: E24; U/M: EA; AEC Category: Q200
R16 = CRCW04024K99FKED: RES, 4.99 k, 1%, 0.063 W, 0402; Manufacturer: Vishay-Dale; CompType: Resistor; Value: 4.99k; Res_ohm: 4990; Value_Code: 4k99; Tolerance_%: 1; Power_W: 0.063; Value2: 0.063W; VDC_V: 50; TempCo: 100 ppm/C; EIA_Code: E96; U/M: EA; AEC Category: Q200
R17 = CRCW04029K53FKED: RES, 9.53 k, 1%, 0.063 W, 0402; Manufacturer: Vishay-Dale; CompType: Resistor; Value: 9.53k; Res_ohm: 9530; Value_Code: 9k53; Tolerance_%: 1; Power_W: 0.063; Value2: 0.063W; VDC_V: 50; TempCo: 100 ppm/C; EIA_Code: E96; U/M: EA; AEC Category: Q200
R18 = CRCW04021K00FKED: RES, 1.00 k, 1%, 0.063 W, 0402; Manufacturer: Vishay-Dale; CompType: Resistor; Value: 1.00k; Res_ohm: 1000; Value_Code: 1k00; Tolerance_%: 1; Power_W: 0.063; Value2: 0.063W; VDC_V: 50; TempCo: 100 ppm/C; EIA_Code: E96; U/M: EA; AEC Category: Q200
R19-R21 = CRCW04024K70JNED: RES, 4.7 k, 5%, 0.063 W, 0402; Manufacturer: Vishay-Dale; CompType: Resistor; Value: 4.7k; Res_ohm: 4700; Value_Code: 4k70; Tolerance_%: 5; Power_W: 0.063; Value2: 0.063W; VDC_V: 50; TempCo: 200 ppm/C; EIA_Code: E24; U/M: EA; AEC Category: Q200
R22 R23 R26 = CRCW060310K0FKEA: RES, 10.0k ohm, 1%, 0.1W, 0603; Manufacturer: Vishay-Dale; CompType: Resistor; Res_ohm: 10000; Value_Code: 10k0; Tolerance_%: 1; Power_W: 0.1; VDC_V: 75; TempCo: 100 ppm/C; EIA_Code: E96; U/M: EA
R24 = CRCW040290K9FKED: RES, 90.9 k, 1%, 0.063 W, 0402; Manufacturer: Vishay-Dale; CompType: Resistor; Value: 90.9k; Res_ohm: 90900; Value_Code: 90k9; Tolerance_%: 1; Power_W: 0.063; Value2: 0.063W; VDC_V: 50; TempCo: 100 ppm/C; EIA_Code: E96; U/M: EA; AEC Category: Q200
R25 = CRCW040210K0DHEDP: RES, 10.0 k, 0.5%, 0.063 W, 0402; Manufacturer: Vishay-Dale; CompType: Resistor; Value: 10.0k; Res_ohm: 10000; Value_Code: 10k0; Tolerance_%: 0.5; Power_W: 0.063; Value2: 0.063W; VDC_V: 50; TempCo: 50 ppm/C; EIA_Code: E192; U/M: EA; AEC Category: Q200
R27 R28 R31 = CRCW0402165RFKED: RES, 165, 1%, 0.063 W, 0402; Manufacturer: Vishay-Dale; CompType: Resistor; Value: 165; Value_Code: 165R; Tolerance_%: 1; Power_W: 0.063; Value2: 0.063W; VDC_V: 50; TempCo: 100 ppm/C; EIA_Code: E96; U/M: EA; AEC Category: Q200
S1 = GPB527C202BR: SWITCH PUSH SPST-NO 10A 125V; Manufacturer: CW Industries; SymbolVersion: use current date i.e. 2008-05-20; SymbolCreator: Use a-id; CompType: Used in some BOM reports.  Useful for finding later.; U/M: EA, IN, or GM
S2 S3 = KSR221GLFS: Switch, Normally open, 2.3N force, 200k operations, SMD; Manufacturer: C&K Components; Circuit: SPST Switch; VDC_V: 32; SwitchFunction: Off-Mom; PositionCount: 1; CurrentRating_mA: 1001
TP1 = 5000: Test Point, Miniature, Red, TH; Manufacturer: Keystone; CompType: Test Point Loop; U/M: EA
U1-U3 = TPD3S714QDBQRQ1: AUTOMOTIVE USB 2.0 Interface Protection with Short-to-Battery and Short-to-Ground Protection, DBQ0016A; Manufacturer: Texas Instruments; SymbolCreator: x0208326; CompType: IC; U/M: EA
U4 = TSB41AB1PHPG4: 400 Mbps IEEE 1394a One-Port Cable Transceiver / Arbiter, 3.3V, 0 to 70 degC, 48-Pin HTQFP (PHP), Green (RoHS & no Sb/Br); Manufacturer: Texas Instruments; Alternate PartNumber: Equivalent; SubFamily: 1394 Physical Layer Controller; Speed(Max)(Mbps): 400; Ports: 1; Supply Voltage(s)(V): 3.3; 1394: True; Rating: Catalog
U5 = LMR14030SDDAR: SIMPLE SWITCHER 40 V 3.5 A, 2.2 MHz Step-Down Converter with 40 µA IQ, DDA0008E; Manufacturer: Texas Instruments; SymbolCreator: Altium; CompType: IC; U/M: EA
U6 = TPS7A4533DCQR: Single Output Fast Transient Response LDO, 1.5 A, Fixed 3.3 V Output, 2.1 to 20 V Input, 6-pin SOT-223 (DCQ), -40 to 125 degC, Green (RoHS & no Sb/Br); Manufacturer: Texas Instruments; Alternate PartNumber: Equivalent; Accuracy(%): 1; Fixed Output Options(V): 3.3; Iout(Max)(A): 1.5; SubFamily: Single Channel LDO; Vdo(Typ)(mV): 300; Vin(Max)(V): 20; Vin(Min)(V): 2.1
U7 = TPS74801RGWR: Single Output LDO, 1.5 A, Adjustable 0.8 to 3.6 V Output, 0.8 to 5.5 V Input, with Programmable Soft Start, 20-pin VQFN (RGW), -40 to 125 degC, Green (RoHS & no Sb/Br); Manufacturer: Texas Instruments; Alternate PartNumber: Equivalent; Accuracy(%): 2; Iout(Max)(A): 1.5; Iq(Typ)(mA): 1; Power Good: TRUE; Rating: Catalog; SubFamily: Single Channel LDO; Vdo(Typ)(mV): 60; Vin(Max)(V): 5.5; Vin(Min)(V): 0.8; Vout Adj(Max)(V): 3.6
U8 U9 U17 = SN74LVC1G125DCKR: Single Bus Buffer Gate With 3-State Output, DCK0005A; Alternate PartNumber: SN74LVC1G125DCKT; Manufacturer: Texas Instruments; SymbolCreator: Altium; CompType: IC; U/M: EA
U11 U12 = ACS712ELCTR-20A-T: Fully Integrated, Hall Effect-Based Linear Current Sensor IC with 2.1kVRMS Isolation and a Low-Resistance Current Conductor, SOIC-8; Manufacturer: Allegro Microsystems Inc; SymbolCreator: Altium
U13-U16 = TPD1E10B06DPYR: ESD in 0402 Package with 10 pF Capacitance and 6 V Breakdown, 1 Channel, -40 to +125 degC, 2-pin X2SON (DPY), Green (RoHS & no Sb/Br); Manufacturer: Texas Instruments; Alternate PartNumber: Equivalent; Breakdown Voltage(Min)(V): 6; Eco-Plan: TBD; IEC 61000-4-2 Air-Gap(+/- kV): 30; IO Capacitance(Typ)(pF): 10; SubFamily: ESD Solution
Y1 = ECS-240-20-5PX-TR: Crystal, 24.000MHz, 20pF, SMD; Manufacturer: CTS Freq Controls; SymbolCreator: a0412235; U/M: EA; TaMin_C: -10; TaMax_C: 70; Frequency Stability: ±50ppm

## Sheet TIDA-00845_TID_Hardware.SchDoc
size 431 x 279 mm; Date: Not shown in title block; ApprovedBy: Not shown in title block; CheckedBy: Not shown in title block; Author: Not shown in title block; CompanyName: Not shown in title block; Engineer: Not shown in title block; Organization: Not shown in title block; Address1: Not shown in title block; Address2: Not shown in title block; Address3: Not shown in title block; Address4: Not shown in title block; DocumentNumber: 1; Revision: Use project parameter SCH_Rev; SheetNumber: 3; SheetTotal: 3; PageSetup: Record=PageOptions¦CenterHorizontal=True¦CenterVertical=True¦PrintScale=1.00¦XCorrection=1.00¦YCorrection=1.00¦PrintKind=0¦BorderSize=5000000¦LeftOffset=0¦BottomOffset=0¦Orientation=2¦PaperLength=1000¦PaperWidth=1000¦Scale=100¦PaperSource=15¦PrintQuality=600¦MediaType=1¦DitherType=10¦PaperKind=Letter¦PrintScaleMode=1
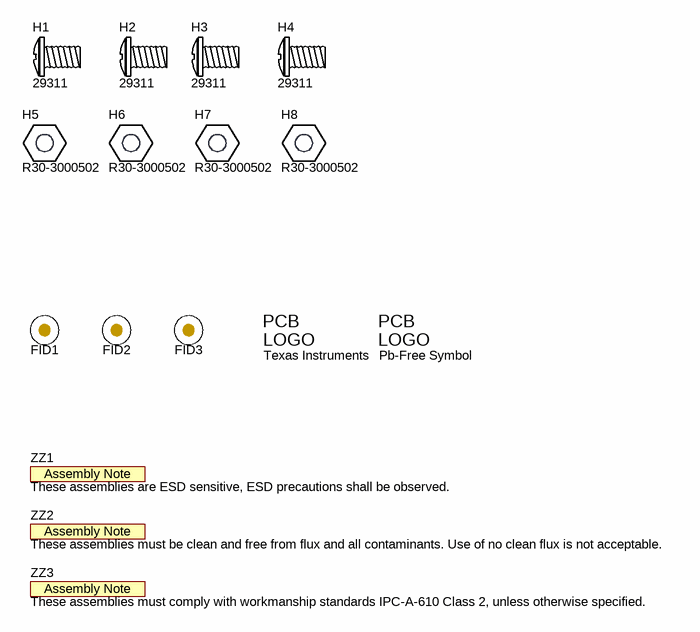
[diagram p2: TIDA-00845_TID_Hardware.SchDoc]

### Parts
FID1  Fiducial  [Fiducial10-20]  (value not drawn)
FID2  Fiducial  [Fiducial10-20]  (value not drawn)
FID3  Fiducial  [Fiducial10-20]  (value not drawn)
H1  29311  [Keystone29311]
H2  29311  [Keystone29311]
H3  29311  [Keystone29311]
H4  29311  [Keystone29311]
H5  R30-3000502  [Harwin_R30-3000502]
H6  R30-3000502  [Harwin_R30-3000502]
H7  R30-3000502  [Harwin_R30-3000502]
H8  R30-3000502  [Harwin_R30-3000502]
Logo1  Texas Instruments  [TI_Horizontal_Overlay_Medium]  (no BOM)
Logo2  Pb-Free Symbol  [Pb-Free_Overlay_Small]  (no BOM)
ZZ1  These assemblies are ESD sensitive, ESD precautions shall be observed.  [AssemblyNote]  (no BOM)
ZZ2  These assemblies must be clean and free from flux and all contaminants. Use of no clean flux is not acceptable.  [AssemblyNote]  (no BOM)
ZZ3  These assemblies must comply with workmanship standards IPC-A-610 Class 2, unless otherwise specified.  [AssemblyNote]  (no BOM)

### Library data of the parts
FID1-FID3 = Fiducial: Fiducial mark.  There is nothing to buy or mount.; SymbolCreator: codlsc
H1-H4 = 29311: Screw Pan Head M3; Manufacturer: Keystone; SymbolCreator: a0412235; CompType: Hardware
H5-H8 = R30-3000502: HEX STANDOFF M3 BRASS 5MM; Manufacturer: Harwin; SymbolCreator: a0412235
Logo1 = TI_Logo: Texas Instrument Corporate Signature; SymbolCreator: a0412235
Logo2 = Pb-Free: SymbolCreator: a0412235
ZZ1-ZZ3 = AssemblyNote: SymbolCreator: codlsc

## Sheet TIDA-00845_Enclosure_Machining.SchDoc
size 1143 x 698 mm; Date: Not shown in title block; ApprovedBy: Not shown in title block; CheckedBy: Not shown in title block; Author: Not shown in title block; CompanyName: Not shown in title block; Engineer: Not shown in title block; Organization: Not shown in title block; Address1: Not shown in title block; Address2: Not shown in title block; Address3: Not shown in title block; Address4: Not shown in title block; DocumentNumber: 1; Revision: Use project parameter SCH_Rev; SheetNumber: 2; SheetTotal: 3; PageSetup: Record=PageOptions¦CenterHorizontal=True¦CenterVertical=True¦PrintScale=1.00¦XCorrection=1.00¦YCorrection=1.00¦PrintKind=0¦BorderSize=5000000¦LeftOffset=0¦BottomOffset=0¦Orientation=2¦PaperLength=1000¦PaperWidth=1000¦Scale=100¦PaperSource=15¦PrintQuality=600¦MediaType=1¦DitherType=10¦PaperKind=Letter¦PrintScaleMode=1

## Sheet TIDA-00845_Enclosure.SchDoc
size 1143 x 698 mm; Date: Not shown in title block; ApprovedBy: Not shown in title block; CheckedBy: Not shown in title block; Author: Not shown in title block; CompanyName: Not shown in title block; Engineer: Not shown in title block; Organization: Not shown in title block; Address1: Not shown in title block; Address2: Not shown in title block; Address3: Not shown in title block; Address4: Not shown in title block; DocumentNumber: 1; Revision: Use project parameter SCH_Rev; SheetNumber: 2; SheetTotal: 3; PageSetup: Record=PageOptions¦CenterHorizontal=True¦CenterVertical=True¦PrintScale=1.00¦XCorrection=1.00¦YCorrection=1.00¦PrintKind=0¦BorderSize=5000000¦LeftOffset=0¦BottomOffset=0¦Orientation=2¦PaperLength=1000¦PaperWidth=1000¦Scale=100¦PaperSource=15¦PrintQuality=600¦MediaType=1¦DitherType=10¦PaperKind=Letter¦PrintScaleMode=1

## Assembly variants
001: not fitted FID1 FID2 FID3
